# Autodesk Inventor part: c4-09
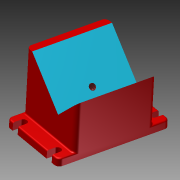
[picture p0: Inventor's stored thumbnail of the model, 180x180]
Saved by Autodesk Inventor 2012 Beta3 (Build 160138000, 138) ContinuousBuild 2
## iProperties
Created: 2010-11
Part Number: c4-09
Material: Default
Document SubType Name: Modeling
Designer: Beta-8540w
Density: 1 g/cm^3
Author: Beta-8540w
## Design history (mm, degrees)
sketch "Sketch1"
  geometry: L1 (-45, 0)-(45, 0); L2 (45, 0)-(45, 10); L3 (45, 10)-(-45, 10); L4 (-45, 10)-(-45, 0); L5 (-45, 10)-(-45, 90); L6 (-45, 90)-(-35, 90); L7 (-35, 90)-(14.497, 40.503); L8 (14.497, 40.503)-(45, 71.005); L9 (45, 71.005)-(45, 10); 2 further points
  constraints: 18 end point, 4 perpendicular, 3 collinear, 2 parallel, 2 point on line, 1 coincident, 1 horizontal, 1 midpoint
  dimensions: "d0" = 90 distance of L3.end L2.end; "d1" = 10 distance of L2.end L1.end; "d2" = 80 distance of L5.start L5.end; "d3" = 10 distance of L5.end L6.end; "d4" = 70 distance of L6.end L7.end; "d5" = 135 deg angle of L6 L7
extrude "Extrusion1" new body sketch "Sketch1" stored distance "d8" = 100; taper "d9" = 0 deg
extrude "Extrusion2" join sketch "Sketch1" stored distance "d10" = 140; taper "d11" = 0 deg
fillet "Fillet1" dims "d12" = 6
fillet "Fillet2" dims "d13" = 2
sketch "Sketch2"
  geometry: L1 (78, -2)-(0, -2) reference; L2 (-6, 4)-(-6, 132) reference; L3 (4.5, -2)-(13.5, -2); L4 (13.5, -2)-(13.5, 8); L5 (13.5, 8)-(4.5, 8); L6 (4.5, 8)-(4.5, -2); 2 further points
  constraints: 8 end point, 2 parallel, 1 horizontal, 1 horizontal alignment, 1 midpoint, 1 perpendicular, 1 point on line, 2 other
  dimensions: "d14" = 9 distance of L5.end L4.end; "d15" = 10 distance of L4.end L3.end; "d16" = 15 distance from line of point (9, 8) L2
extrude "Extrusion3" cut sketch "Sketch2" stored distance "d17" = 140; taper "d18" = 0 deg
mirror "Mirror1"
mirror "Mirror2"
hole "Hole1" diameter "d21" = 8.376; stored, may be unused: countersink angle "d25" = 90 deg, drill point angle "d27" = 118 deg; dims "d19" = 50, "d20" = 15, "d22" = 30, "d23" = 4, "d24" = 2, "d26" = 33.5
body "Solid1"
